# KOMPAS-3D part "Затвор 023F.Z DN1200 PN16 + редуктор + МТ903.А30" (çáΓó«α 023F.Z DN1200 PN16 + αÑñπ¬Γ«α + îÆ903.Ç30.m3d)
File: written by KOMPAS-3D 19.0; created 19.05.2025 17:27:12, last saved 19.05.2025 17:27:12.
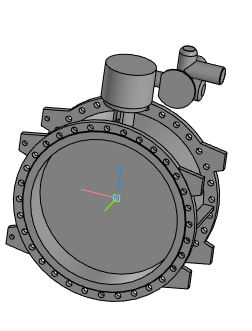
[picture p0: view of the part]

Document properties: Полное имя файла: Затвор 023F.Z DN1200 PN16 + редуктор + МТ903.А30.a3d

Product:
- Part/product: Затвор 023F.Z DN1200 PN16 + редуктор + МТ903.А30
    Масса: 2369.94

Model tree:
1. Операция без истории:1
